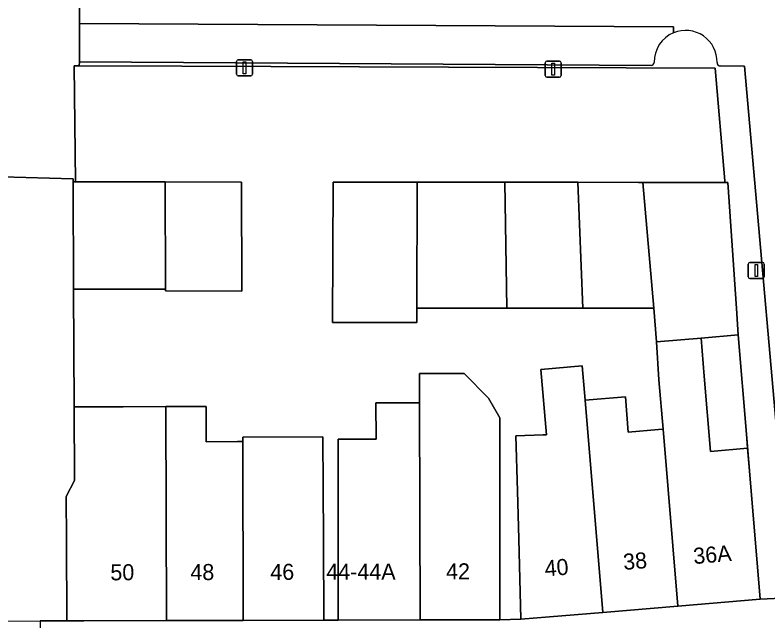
# Model space of a CAD drawing. Extents: x 160023 to 161302, y 384750 to 385707.
# Drawn here: x 160553.5 to 160600.36, y 384816.85 to 384854.59 of the extents above; entities that cross this region are included whole.
import ezdxf

# ---------------------------------------------------------------- set-up
doc = ezdxf.new("R2010")
doc.units = 0
for name, color, linetype in [('IMGEO_Erf', 7, 'Continuous'), ('IMGEO_Lichtmast', 7, 'Continuous'), ('IMGEO_Muur', 7, 'Continuous'), ('IMGEO_Pand', 7, 'Continuous'), ('IMGEO_Pand_nummerreeks', 7, 'Continuous'), ('IMGEO_Parkeervlak_open', 7, 'Continuous'), ('IMGEO_Rijbaan_lokaal_open', 7, 'Continuous'), ('IMGEO_Voetpad_open', 7, 'Continuous')]:
    doc.layers.add(name, color=color, linetype=linetype)

msp = doc.modelspace()

# ---------------------------------------------------------------- linework, layer by layer
at = {"layer": 'IMGEO_Erf'}
msp.add_lwpolyline([(160548.25, 384844.629), (160557.109, 384844.386), (160557.11, 384844.2), (160557.265, 384844.2), (160557.171, 384851.43), (160557.497, 384851.429), (160557.498, 384851.665), (160557.513, 384854.069), (160557.552, 384860.073), (160557.586, 384865.479), (160597.35, 384865.241), (160597.351, 384859.843), (160597.351, 384859.526)], dxfattribs=at)
for points in [[(160593.426, 384834.233), (160593.248, 384836.326), (160588.84, 384836.33), (160584.102, 384836.335), (160578.862, 384836.34), (160578.508, 384836.34), (160578.507, 384835.438), (160573.263, 384835.442), (160573.304, 384844.185), (160578.516, 384844.18), (160583.983, 384844.174), (160588.535, 384844.17), (160592.298, 384844.167), (160592.58, 384844.166), (160597.695, 384844.161), (160597.686, 384844.27), (160597.07, 384851.273), (160563.878, 384851.404), (160557.497, 384851.429), (160557.171, 384851.43), (160557.265, 384844.2), (160562.835, 384844.194), (160567.59, 384844.19), (160567.615, 384837.401), (160562.865, 384837.405), (160562.865, 384837.52), (160562.735, 384837.52), (160557.143, 384837.526), (160557.18, 384830.183), (160560.233, 384830.196), (160562.884, 384830.207), (160565.385, 384830.217), (160565.394, 384828.018), (160567.348, 384828.026), (160567.669, 384828.027), (160567.668, 384828.306), (160572.664, 384828.326), (160572.676, 384825.199), (160572.689, 384821.898), (160572.708, 384816.898), (160573.61, 384816.901), (160573.617, 384828.169), (160575.964, 384828.18), (160575.962, 384830.442), (160578.666, 384830.445), (160578.665, 384832.258), (160581.449, 384832.273), (160582.965, 384830.729), (160583.667, 384829.495), (160583.671, 384824.799), (160583.674, 384821.928), (160583.678, 384816.928), (160584.984, 384816.963), (160584.846, 384821.962), (160584.764, 384824.929), (160584.668, 384828.387), (160586.379, 384828.435), (160586.57, 384828.44), (160586.229, 384832.522), (160588.797, 384832.737), (160588.976, 384830.594), (160591.486, 384830.804), (160591.668, 384828.619), (160593.549, 384828.776), (160593.836, 384828.8), (160593.579, 384831.87)], [(160598.51, 384834.666), (160596.202, 384834.47), (160596.399, 384832.106), (160596.791, 384827.416), (160599.091, 384827.608), (160599.033, 384828.496)]]:
    msp.add_lwpolyline(points, close=True, dxfattribs=at)
at = {"layer": 'IMGEO_Lichtmast'}
for p, q in [((160567.284, 384850.904), (160567.284, 384851.704)), ((160567.284, 384851.704), (160567.284, 384850.904)), ((160567.384, 384851.804), (160568.174, 384851.804)), ((160568.174, 384851.804), (160567.384, 384851.804)), ((160568.274, 384851.704), (160568.274, 384850.904)), ((160568.274, 384850.904), (160568.274, 384851.704)), ((160586.597, 384851.72), (160587.387, 384851.72)), ((160587.387, 384851.72), (160586.597, 384851.72)), ((160586.497, 384850.82), (160586.497, 384851.62)), ((160586.497, 384851.62), (160586.497, 384850.82)), ((160587.487, 384851.62), (160587.487, 384850.82)), ((160587.487, 384850.82), (160587.487, 384851.62)), ((160568.174, 384850.804), (160567.384, 384850.804)), ((160567.384, 384850.804), (160568.174, 384850.804)), ((160587.387, 384850.72), (160586.597, 384850.72)), ((160586.597, 384850.72), (160587.387, 384850.72)), ((160599.138, 384838.282), (160599.138, 384839.082)), ((160599.138, 384839.082), (160599.138, 384838.282)), ((160599.238, 384839.182), (160600.028, 384839.182)), ((160600.028, 384839.182), (160599.238, 384839.182)), ((160600.128, 384839.082), (160600.128, 384838.282)), ((160600.128, 384838.282), (160600.128, 384839.082)), ((160600.028, 384838.182), (160599.238, 384838.182)), ((160599.238, 384838.182), (160600.028, 384838.182))]:
    msp.add_line(p, q, dxfattribs=at)
for points in [[(160567.704, 384851.679), (160567.854, 384851.679), (160567.854, 384850.929), (160567.704, 384850.929), (160567.704, 384851.679)], [(160586.917, 384851.595), (160587.067, 384851.595), (160587.067, 384850.845), (160586.917, 384850.845), (160586.917, 384851.595)], [(160599.558, 384839.057), (160599.708, 384839.057), (160599.708, 384838.307), (160599.558, 384838.307), (160599.558, 384839.057)]]:
    msp.add_lwpolyline(points, dxfattribs=at)
for centre, start, end in [((160567.384, 384851.704), 90, 180), ((160567.384, 384851.704), 90, 180), ((160568.174, 384851.704), 0, 90), ((160568.174, 384851.704), 360, 90), ((160586.597, 384851.62), 90, 180), ((160586.597, 384851.62), 90, 180), ((160587.387, 384851.62), 0, 90), ((160587.387, 384851.62), 360, 90), ((160567.384, 384850.904), 180, 270), ((160567.384, 384850.904), 180, 270), ((160568.174, 384850.904), 270, 0), ((160568.174, 384850.904), 270, 0), ((160586.597, 384850.82), 180, 270), ((160586.597, 384850.82), 180, 270), ((160587.387, 384850.82), 270, 0), ((160587.387, 384850.82), 270, 0), ((160599.238, 384839.082), 90, 180), ((160599.238, 384839.082), 90, 180), ((160600.028, 384839.082), 0, 90), ((160600.028, 384839.082), 360, 90), ((160599.238, 384838.282), 180, 270), ((160599.238, 384838.282), 180, 270), ((160600.028, 384838.282), 270, 0), ((160600.028, 384838.282), 270, 0)]:
    msp.add_arc(centre, 0.1, start, end, dxfattribs=at)
at = {"layer": 'IMGEO_Muur'}
msp.add_lwpolyline([(160599.033, 384828.496), (160599.209, 384826.202)], dxfattribs=at)
at = {"layer": 'IMGEO_Pand'}
for points in [[(160557.202, 384825.595), (160557.18, 384830.183), (160557.143, 384837.526), (160557.11, 384844.2), (160557.109, 384844.386), (160548.25, 384844.629), (160547.311, 384846.607), (160537.567, 384846.953), (160535.49, 384845.715), (160531.804, 384843.523), (160538.028, 384832.564), (160545.657, 384832.593), (160545.679, 384828.065), (160545.681, 384827.685), (160545.734, 384816.779), (160551.363, 384816.841), (160551.838, 384816.842), (160555.07, 384816.851), (160556.721, 384816.856), (160556.697, 384821.856), (160556.683, 384824.599)], [(160562.835, 384844.194), (160557.265, 384844.2), (160557.11, 384844.2), (160557.143, 384837.526), (160562.735, 384837.52), (160562.865, 384837.52)], [(160562.835, 384844.194), (160562.865, 384837.52), (160562.865, 384837.405), (160567.615, 384837.401), (160567.59, 384844.19)], [(160578.516, 384844.18), (160573.304, 384844.185), (160573.263, 384835.442), (160578.507, 384835.438), (160578.508, 384836.34)], [(160583.983, 384844.174), (160578.516, 384844.18), (160578.508, 384836.34), (160578.862, 384836.34), (160584.102, 384836.335)], [(160588.535, 384844.17), (160583.983, 384844.174), (160584.102, 384836.335), (160588.84, 384836.33)], [(160592.58, 384844.166), (160592.298, 384844.167), (160588.535, 384844.17), (160588.84, 384836.33), (160593.248, 384836.326)], [(160597.695, 384844.161), (160592.58, 384844.166), (160593.248, 384836.326), (160593.426, 384834.233), (160596.202, 384834.47), (160598.51, 384834.666), (160598.397, 384836.321), (160597.858, 384844.161)], [(160599.209, 384826.202), (160599.091, 384827.608), (160596.791, 384827.416), (160596.399, 384832.106), (160596.202, 384834.47), (160593.426, 384834.233), (160593.579, 384831.87), (160593.836, 384828.8), (160594.757, 384817.78), (160599.877, 384818.208)], [(160588.976, 384830.594), (160588.797, 384832.737), (160586.229, 384832.522), (160586.57, 384828.44), (160586.379, 384828.435), (160584.668, 384828.387), (160584.764, 384824.929), (160584.846, 384821.962), (160584.984, 384816.963), (160590.08, 384817.389)], [(160583.678, 384816.928), (160583.674, 384821.928), (160583.671, 384824.799), (160583.667, 384829.495), (160582.965, 384830.729), (160581.449, 384832.273), (160578.665, 384832.258), (160578.666, 384830.445), (160578.706, 384816.915)], [(160593.836, 384828.8), (160593.549, 384828.776), (160591.668, 384828.619), (160591.486, 384830.804), (160588.976, 384830.594), (160590.08, 384817.389), (160594.757, 384817.78)], [(160562.884, 384830.207), (160560.233, 384830.196), (160557.18, 384830.183), (160557.202, 384825.595), (160556.683, 384824.599), (160556.697, 384821.856), (160556.721, 384816.856), (160557.771, 384816.858), (160562.92, 384816.872)], [(160567.669, 384828.027), (160567.348, 384828.026), (160565.394, 384828.018), (160565.385, 384830.217), (160562.884, 384830.207), (160562.92, 384816.872), (160567.702, 384816.885)], [(160575.962, 384830.442), (160575.964, 384828.18), (160573.617, 384828.169), (160573.61, 384816.901), (160578.706, 384816.915), (160578.666, 384830.445)], [(160572.676, 384825.199), (160572.664, 384828.326), (160567.668, 384828.306), (160567.669, 384828.027), (160567.702, 384816.885), (160572.708, 384816.898), (160572.689, 384821.898)]]:
    msp.add_lwpolyline(points, close=True, dxfattribs=at)
at = {"layer": 'IMGEO_Parkeervlak_open'}
msp.add_lwpolyline([(160594.49, 384853.482), (160594.473, 384853.852), (160557.513, 384854.069), (160557.498, 384851.665), (160593.083, 384851.456)], dxfattribs=at)
for centre, radius, start, end in [((160595.235, 384851.666), 1.963, 112.3195, 180.8897), ((160593.095, 384851.633), 0.178, 265.9933, 0.9104)]:
    msp.add_arc(centre, radius, start, end, dxfattribs=at)
at = {"layer": 'IMGEO_Rijbaan_lokaal_open'}
for points in [[(160597.351, 384859.526), (160597.351, 384859.843), (160557.552, 384860.073), (160557.513, 384854.069), (160594.473, 384853.852), (160594.49, 384853.482)], [(160597.394, 384851.417), (160598.909, 384851.411), (160601.61, 384820.597), (160604.414, 384820.845), (160608.217, 384821.182), (160608.145, 384822.259), (160606.374, 384822.087), (160604.917, 384838.539)]]:
    msp.add_lwpolyline(points, dxfattribs=at)
for centre, radius, start, end in [((160595.236, 384851.667), 1.962, 358.8186, 112.3388), ((160597.395, 384851.616), 0.199, 176.693, 269.6481)]:
    msp.add_arc(centre, radius, start, end, dxfattribs=at)
at = {"layer": 'IMGEO_Voetpad_open'}
for points in [[(160593.083, 384851.456), (160557.498, 384851.665), (160557.497, 384851.429), (160563.878, 384851.404), (160597.07, 384851.273), (160597.686, 384844.27), (160597.695, 384844.161), (160597.858, 384844.161), (160598.397, 384836.321), (160598.51, 384834.666), (160599.033, 384828.496), (160599.091, 384827.608), (160599.209, 384826.202), (160599.877, 384818.208), (160604.686, 384818.432), (160604.414, 384820.845), (160601.61, 384820.597), (160598.909, 384851.411)], [(160598.909, 384851.411), (160597.394, 384851.417)], [(160604.686, 384818.432), (160599.877, 384818.208), (160594.757, 384817.78), (160590.08, 384817.389), (160584.984, 384816.963), (160583.678, 384816.928), (160578.706, 384816.915), (160573.61, 384816.901), (160572.708, 384816.898), (160567.702, 384816.885), (160562.92, 384816.872), (160557.771, 384816.858), (160556.721, 384816.856), (160555.07, 384816.851), (160555.053, 384813.866), (160564.61, 384813.996)]]:
    msp.add_lwpolyline(points, dxfattribs=at)
for centre, radius, start, end in [((160595.236, 384851.667), 1.962, 358.8186, 112.3388), ((160595.235, 384851.666), 1.963, 112.3195, 180.8897), ((160593.095, 384851.633), 0.178, 265.9933, 0.9104), ((160597.395, 384851.616), 0.199, 176.693, 269.6481)]:
    msp.add_arc(centre, radius, start, end, dxfattribs=at)

# ---------------------------------------------------------------- texts
at = {"layer": 'IMGEO_Pand_nummerreeks'}
for s, rotation, p in [('36A', 4.7785, (160595.755, 384820.393)), ('38', 4.7785, (160591.388, 384820.027)), ('50', 0.1547, (160559.431, 384819.383)), ('48', 0.1547, (160564.41, 384819.396)), ('46', 0.1547, (160569.386, 384819.409)), ('44-44A', 0.1574, (160572.872, 384819.419)), ('42', 0.1537, (160580.325, 384819.439)), ('40', 4.7785, (160586.501, 384819.619))]:
    msp.add_text(s, height=1, rotation=rotation, dxfattribs=at).set_placement(p)

doc.saveas('drawing.dxf')
